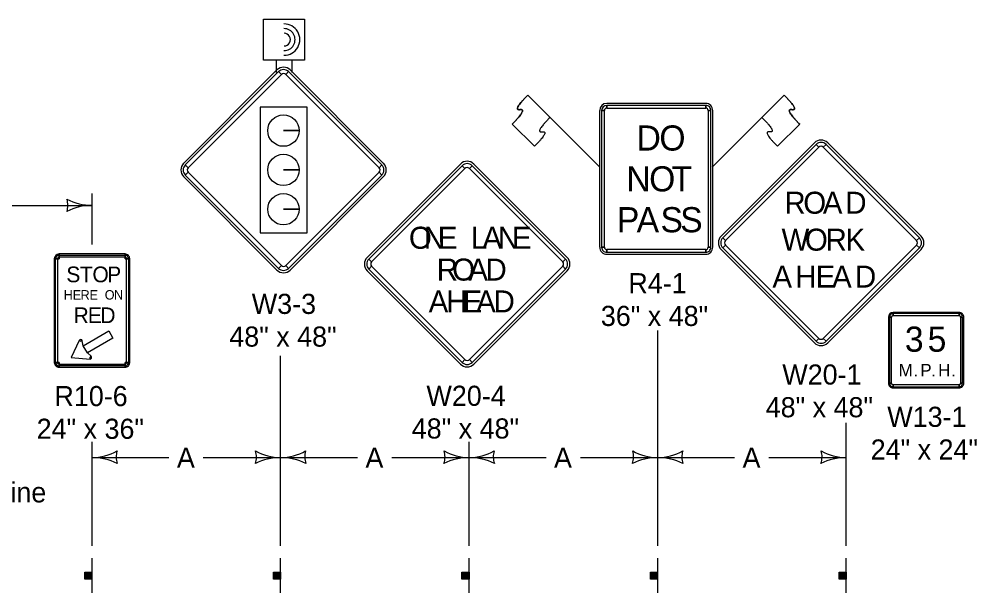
# Model space of a CAD drawing. Extents: x 10124 to 16850, y 7924 to 12166.
# Drawn here: x 16036 to 16798, y 9435 to 9891 of the extents above; entities that cross this region are included whole.
import ezdxf

# ---------------------------------------------------------------- set-up
doc = ezdxf.new("R2010")
doc.units = 0
for name, color, linetype in [('dsnCellElements', 7, 'Continuous'), ('dsnStdLabel', 7, 'Continuous'), ('Level 2', 7, 'Continuous'), ('Level 5', 7, 'Continuous')]:
    doc.layers.add(name, color=color, linetype=linetype)

msp = doc.modelspace()

# ---------------------------------------------------------------- linework, layer by layer
at = {"layer": 'dsnCellElements'}
for centre, radius, start, end in [((16058.64, 9742.96), 16.42, 342.26665, 17.73335), ((16094.27, 9785.46), 42.5, 241.92751, 270), ((16094.27, 9700.46), 42.5, 90, 118.07249)]:
    msp.add_arc(centre, radius, start, end, dxfattribs=at)
at = {"layer": 'dsnStdLabel'}
for p, q in [((16241.35, 9850.62), (16167.1, 9776.37)), ((16242.67, 9849.29), (16244.88, 9847.08)), ((16248.42, 9847.08), (16250.63, 9849.29)), ((16326.2, 9776.37), (16251.95, 9850.62)), ((16498.25, 9773.27), (16440.92, 9830.57)), ((16440.92, 9830.57), (16458.61, 9812.89)), ((16587.55, 9773.27), (16644.87, 9830.58)), ((16644.87, 9830.58), (16627.18, 9812.9)), ((16582.5, 9824.03), (16503.75, 9824.03)), ((16503.75, 9820.28), (16503.75, 9822.46)), ((16582.5, 9822.46), (16582.5, 9820.28)), ((16498.12, 9818.4), (16498.12, 9709.65)), ((16499.68, 9818.4), (16501.87, 9818.4)), ((16584.37, 9818.4), (16586.56, 9818.4)), ((16588.12, 9709.65), (16588.12, 9818.4)), ((16446.23, 9789.9), (16428.55, 9807.57)), ((16639.57, 9789.91), (16657.24, 9807.59)), ((16259.06, 9802.4), (16246.56, 9802.4)), ((16246.56, 9802.4), (16259.06, 9802.4)), ((16668.97, 9792.72), (16594.72, 9718.47)), ((16670.29, 9791.39), (16672.5, 9789.18)), ((16676.04, 9789.18), (16678.25, 9791.39)), ((16753.82, 9718.47), (16679.57, 9792.72)), ((16387.38, 9775.8), (16313.14, 9701.55)), ((16472.24, 9701.55), (16397.99, 9775.8)), ((16170.63, 9772.84), (16168.42, 9775.05)), ((16168.42, 9767.09), (16170.63, 9769.3)), ((16259.06, 9771.15), (16246.56, 9771.15)), ((16246.56, 9771.15), (16259.06, 9771.15)), ((16324.87, 9775.05), (16322.66, 9772.84)), ((16322.66, 9769.3), (16324.87, 9767.09)), ((16388.71, 9774.48), (16390.92, 9772.27)), ((16394.45, 9772.27), (16396.66, 9774.48)), ((16167.1, 9765.77), (16241.35, 9691.52)), ((16251.95, 9691.52), (16326.2, 9765.77)), ((16259.06, 9739.9), (16246.56, 9739.9)), ((16246.56, 9739.9), (16259.06, 9739.9)), ((16598.26, 9714.94), (16596.05, 9717.15)), ((16752.49, 9717.15), (16750.29, 9714.94)), ((16501.87, 9709.65), (16499.68, 9709.65)), ((16503.75, 9705.59), (16503.75, 9707.78)), ((16582.5, 9707.78), (16582.5, 9705.59)), ((16586.56, 9709.65), (16584.37, 9709.65)), ((16594.72, 9707.86), (16668.97, 9633.62)), ((16596.05, 9709.19), (16598.26, 9711.4)), ((16679.57, 9633.62), (16753.82, 9707.86)), ((16750.29, 9711.4), (16752.49, 9709.19)), ((16064.27, 9700.53), (16068.02, 9700.53)), ((16065.21, 9700.53), (16066.77, 9700.53)), ((16068.02, 9700.53), (16068.02, 9704.28)), ((16068.02, 9701.78), (16068.02, 9703.34)), ((16120.52, 9704.28), (16120.52, 9700.53)), ((16120.52, 9703.34), (16120.52, 9701.78)), ((16120.52, 9700.53), (16124.27, 9700.53)), ((16121.77, 9700.53), (16123.34, 9700.53)), ((16316.67, 9698.02), (16314.46, 9700.23)), ((16470.91, 9700.23), (16468.7, 9698.02)), ((16503.75, 9704.03), (16582.5, 9704.03)), ((16244.88, 9695.05), (16242.67, 9692.85)), ((16250.63, 9692.85), (16248.42, 9695.05)), ((16314.46, 9692.27), (16316.67, 9694.48)), ((16468.7, 9694.48), (16470.91, 9692.27)), ((16313.14, 9690.95), (16387.38, 9616.7)), ((16397.99, 9616.7), (16472.24, 9690.95)), ((16727.79, 9654.03), (16727.79, 9601.53)), ((16728.73, 9654.03), (16730.29, 9654.03)), ((16784.04, 9657.78), (16731.54, 9657.78)), ((16731.54, 9655.28), (16731.54, 9656.84)), ((16784.04, 9656.84), (16784.04, 9655.28)), ((16785.29, 9654.03), (16786.85, 9654.03)), ((16787.79, 9601.53), (16787.79, 9654.03)), ((16084.13, 9635.55), (16085.24, 9634.97)), ((16085.24, 9634.97), (16086.46, 9635.24)), ((16672.5, 9637.15), (16670.29, 9634.94)), ((16678.25, 9634.94), (16676.04, 9637.15)), ((16093.58, 9622.9), (16092.74, 9621.98)), ((16068.02, 9618.03), (16064.27, 9618.03)), ((16066.77, 9618.03), (16065.21, 9618.03)), ((16068.02, 9614.28), (16068.02, 9618.03)), ((16068.02, 9615.22), (16068.02, 9616.78)), ((16092.74, 9621.98), (16092.69, 9620.73)), ((16124.27, 9618.03), (16120.52, 9618.03)), ((16120.52, 9618.03), (16120.52, 9614.28)), ((16120.52, 9616.78), (16120.52, 9615.22)), ((16123.34, 9618.03), (16121.77, 9618.03)), ((16390.92, 9620.24), (16388.71, 9618.03)), ((16396.66, 9618.03), (16394.45, 9620.24)), ((16730.29, 9601.53), (16728.73, 9601.53)), ((16731.54, 9598.72), (16731.54, 9600.28)), ((16784.04, 9600.28), (16784.04, 9598.72)), ((16786.85, 9601.53), (16785.29, 9601.53)), ((16731.54, 9597.78), (16784.04, 9597.78))]:
    msp.add_line(p, q, dxfattribs=at)
for points in [[(16242.67, 9849.29), (16168.42, 9775.05), (16170.63, 9772.84), (16244.88, 9847.08), (16242.67, 9849.29)], [(16324.87, 9775.05), (16250.63, 9849.29), (16248.42, 9847.08), (16322.66, 9772.84), (16324.87, 9775.05)], [(16265.38, 9821.01), (16227.92, 9821.01), (16227.92, 9721.12), (16265.38, 9721.12), (16265.38, 9821.01)], [(16582.5, 9822.46), (16503.75, 9822.46), (16503.75, 9820.28), (16582.5, 9820.28), (16582.5, 9822.46)], [(16499.68, 9818.4), (16499.68, 9709.65), (16501.87, 9709.65), (16501.87, 9818.4), (16499.68, 9818.4)], [(16586.56, 9709.65), (16586.56, 9818.4), (16584.37, 9818.4), (16584.37, 9709.65), (16586.56, 9709.65)], [(16670.29, 9791.39), (16596.05, 9717.15), (16598.26, 9714.94), (16672.5, 9789.18), (16670.29, 9791.39)], [(16752.49, 9717.15), (16678.25, 9791.39), (16676.04, 9789.18), (16750.29, 9714.94), (16752.49, 9717.15)], [(16168.42, 9767.09), (16242.67, 9692.85), (16244.88, 9695.05), (16170.63, 9769.3), (16168.42, 9767.09)], [(16250.63, 9692.85), (16324.87, 9767.09), (16322.66, 9769.3), (16248.42, 9695.05), (16250.63, 9692.85)], [(16388.71, 9774.48), (16314.46, 9700.23), (16316.67, 9698.02), (16390.92, 9772.27), (16388.71, 9774.48)], [(16470.91, 9700.23), (16396.66, 9774.48), (16394.45, 9772.27), (16468.7, 9698.02), (16470.91, 9700.23)], [(16503.75, 9705.59), (16582.5, 9705.59), (16582.5, 9707.78), (16503.75, 9707.78), (16503.75, 9705.59)], [(16596.05, 9709.19), (16670.29, 9634.94), (16672.5, 9637.15), (16598.26, 9711.4), (16596.05, 9709.19)], [(16678.25, 9634.94), (16752.49, 9709.19), (16750.29, 9711.4), (16676.04, 9637.15), (16678.25, 9634.94)], [(16068.02, 9614.28), (16120.52, 9614.28), (16120.52, 9618.03), (16124.27, 9618.03), (16124.27, 9700.53), (16120.52, 9700.53), (16120.52, 9704.28), (16068.02, 9704.28), (16068.02, 9700.53), (16064.27, 9700.53), (16064.27, 9618.03), (16068.02, 9618.03), (16068.02, 9614.28)], [(16066.77, 9700.53), (16066.77, 9618.03), (16065.21, 9618.03), (16065.21, 9700.53), (16066.77, 9700.53)], [(16120.52, 9701.78), (16068.02, 9701.78), (16068.02, 9703.34), (16120.52, 9703.34), (16120.52, 9701.78)], [(16121.77, 9618.03), (16121.77, 9700.53), (16123.34, 9700.53), (16123.34, 9618.03), (16121.77, 9618.03)], [(16314.46, 9692.27), (16388.71, 9618.03), (16390.92, 9620.24), (16316.67, 9694.48), (16314.46, 9692.27)], [(16396.66, 9618.03), (16470.91, 9692.27), (16468.7, 9694.48), (16394.45, 9620.24), (16396.66, 9618.03)], [(16728.73, 9654.03), (16728.73, 9601.53), (16730.29, 9601.53), (16730.29, 9654.03), (16728.73, 9654.03)], [(16784.04, 9656.84), (16731.54, 9656.84), (16731.54, 9655.28), (16784.04, 9655.28), (16784.04, 9656.84)], [(16786.85, 9601.53), (16786.85, 9654.03), (16785.29, 9654.03), (16785.29, 9601.53), (16786.85, 9601.53)], [(16107.64, 9643.03), (16110.93, 9637.35), (16090.62, 9625.63), (16087.34, 9631.31), (16107.64, 9643.03)], [(16077.62, 9621.91), (16092.69, 9620.73), (16092.74, 9621.98), (16093.58, 9622.9), (16090.62, 9625.63), (16087.34, 9631.31), (16086.46, 9635.24), (16085.24, 9634.97), (16084.13, 9635.55), (16077.62, 9621.91)], [(16068.02, 9616.78), (16120.52, 9616.78), (16120.52, 9615.22), (16068.02, 9615.22), (16068.02, 9616.78)], [(16731.54, 9598.72), (16784.04, 9598.72), (16784.04, 9600.28), (16731.54, 9600.28), (16731.54, 9598.72)]]:
    msp.add_lwpolyline(points, close=True, dxfattribs=at)
for centre in [(16246.56, 9802.4), (16246.56, 9771.15), (16246.56, 9739.9)]:
    msp.add_circle(centre, 12.5, dxfattribs=at)
for centre, radius, start, end in [((16246.65, 9845.31), 7.5, 44.99999, 134.99974), ((16246.65, 9845.31), 5.62, 44.99999, 134.99974), ((16246.65, 9845.31), 2.5, 44.99999, 134.99974), ((16503.75, 9818.4), 5.62, 90.00021, 179.99985), ((16503.75, 9818.4), 4.06, 90.00021, 179.99985), ((16582.5, 9818.4), 5.62, 0, 90.00021), ((16582.5, 9818.4), 4.06, 0, 90.00021), ((16503.75, 9818.4), 1.87, 90.00021, 179.99985), ((16582.5, 9818.4), 1.87, 0, 90.00021), ((16674.27, 9787.41), 7.5, 44.99999, 134.99974), ((16674.27, 9787.41), 5.62, 44.99999, 134.99974), ((16674.27, 9787.41), 2.5, 44.99999, 134.99974), ((16172.4, 9771.07), 7.5, 134.99974, 224.99995), ((16320.89, 9771.07), 7.5, 315.00016, 44.9998), ((16392.69, 9770.5), 7.5, 44.99999, 134.99974), ((16392.69, 9770.5), 5.62, 44.99999, 134.99974), ((16172.4, 9771.07), 5.62, 134.99974, 224.99995), ((16172.4, 9771.07), 2.5, 134.99974, 224.99995), ((16320.89, 9771.07), 2.5, 315.00016, 44.9998), ((16320.89, 9771.07), 5.62, 315.00016, 44.9998), ((16392.69, 9770.5), 2.5, 44.99999, 134.99974), ((16600.03, 9713.17), 7.5, 134.99974, 224.99995), ((16600.03, 9713.17), 5.62, 134.99974, 224.99995), ((16600.03, 9713.17), 2.5, 134.99974, 224.99995), ((16748.52, 9713.17), 2.5, 315.00016, 44.9998), ((16748.52, 9713.17), 5.62, 315.00016, 44.9998), ((16748.52, 9713.17), 7.5, 315.00016, 44.9998), ((16503.75, 9709.65), 5.62, 179.99985, 270.00006), ((16503.75, 9709.65), 4.06, 179.99985, 270.00006), ((16503.75, 9709.65), 1.87, 179.99985, 270.00006), ((16582.5, 9709.65), 5.62, 270.00006, 0.00027), ((16582.5, 9709.65), 4.06, 270.00006, 0.00027), ((16582.5, 9709.65), 1.87, 270.00006, 0.00027), ((16068.02, 9700.53), 3.75, 90.00021, 179.99985), ((16068.02, 9700.53), 2.81, 90.00021, 179.99985), ((16068.02, 9700.53), 1.25, 90.00021, 179.99985), ((16120.52, 9700.53), 3.75, 0, 90.00021), ((16120.52, 9700.53), 2.81, 0, 90.00021), ((16120.52, 9700.53), 1.25, 0, 90.00021), ((16318.44, 9696.25), 7.5, 134.99974, 224.99995), ((16318.44, 9696.25), 5.62, 134.99974, 224.99995), ((16466.93, 9696.25), 5.62, 315.00016, 44.9998), ((16466.93, 9696.25), 7.5, 315.00016, 44.9998), ((16246.65, 9696.82), 7.5, 224.99995, 315.00016), ((16246.65, 9696.82), 5.62, 224.99995, 315.00016), ((16246.65, 9696.82), 2.5, 224.99995, 315.00016), ((16318.44, 9696.25), 2.5, 134.99974, 224.99995), ((16466.93, 9696.25), 2.5, 315.00016, 44.9998), ((16731.54, 9654.03), 3.75, 90.00021, 179.99985), ((16731.54, 9654.03), 2.81, 90.00021, 179.99985), ((16731.54, 9654.03), 1.25, 90.00021, 179.99985), ((16784.04, 9654.03), 3.75, 0, 90.00021), ((16784.04, 9654.03), 2.81, 0, 90.00021), ((16784.04, 9654.03), 1.25, 0, 90.00021), ((16085.24, 9634.97), 1.25, 12.62232, 152.27557), ((16674.27, 9638.92), 7.5, 224.99995, 315.00016), ((16674.27, 9638.92), 5.62, 224.99995, 315.00016), ((16674.27, 9638.92), 2.5, 224.99995, 315.00016), ((16092.74, 9621.98), 1.25, 267.72427, 47.37758), ((16068.02, 9618.03), 3.75, 179.99985, 270.00006), ((16068.02, 9618.03), 2.81, 179.99985, 270.00006), ((16068.02, 9618.03), 1.25, 179.99985, 270.00006), ((16120.52, 9618.03), 3.75, 270.00006, 0.00027), ((16120.52, 9618.03), 2.81, 270.00006, 0.00027), ((16120.52, 9618.03), 1.25, 270.00006, 0.00027), ((16392.69, 9622.01), 7.5, 224.99995, 315.00016), ((16392.69, 9622.01), 5.62, 224.99995, 315.00016), ((16392.69, 9622.01), 2.5, 224.99995, 315.00016), ((16731.54, 9601.53), 3.75, 179.99985, 270.00006), ((16731.54, 9601.53), 2.81, 179.99985, 270.00006), ((16731.54, 9601.53), 1.25, 179.99985, 270.00006), ((16784.04, 9601.53), 3.75, 270.00006, 0.00027), ((16784.04, 9601.53), 2.81, 270.00006, 0.00027), ((16784.04, 9601.53), 1.25, 270.00006, 0.00027)]:
    msp.add_arc(centre, radius, start, end, dxfattribs=at)
for points in [[(16428.55, 9807.57), (16440.92, 9819.95), (16428.55, 9818.18), (16440.92, 9830.57)], [(16657.24, 9807.59), (16644.87, 9819.97), (16657.24, 9818.2), (16644.87, 9830.58)], [(16458.61, 9812.89), (16446.23, 9800.5), (16458.6, 9802.28), (16446.23, 9789.9)], [(16627.18, 9812.9), (16639.56, 9800.52), (16627.19, 9802.29), (16639.57, 9789.91)]]:
    msp.add_open_spline(points, degree=2, dxfattribs=at)
at = {"layer": 'Level 2'}
for p, q in [((16240.8, 9858.53), (16240.8, 9848.53)), ((16253.3, 9858.53), (16253.3, 9848.53)), ((16094.27, 9711.85), (16094.27, 9752.26)), ((15430.7, 9742.96), (16094.27, 9742.96)), ((16544.27, 9472.29), (16544.27, 9643.52)), ((16244.27, 9472.29), (16244.27, 9623.19)), ((16694.27, 9472.29), (16694.27, 9569.97)), ((16094.27, 9472.29), (16094.27, 9554.79)), ((16394.27, 9472.29), (16394.27, 9554.79)), ((16094.27, 9542.29), (16155.44, 9542.29)), ((16182.78, 9542.29), (16244.27, 9542.29)), ((16244.27, 9542.29), (16305.44, 9542.29)), ((16332.78, 9542.29), (16394.27, 9542.29)), ((16394.27, 9542.29), (16455.44, 9542.29)), ((16482.78, 9542.29), (16544.27, 9542.29)), ((16544.27, 9542.29), (16605.44, 9542.29)), ((16632.78, 9542.29), (16694.27, 9542.29)), ((16094.27, 9434.79), (16094.27, 9462.29)), ((16244.27, 9434.79), (16244.27, 9462.29)), ((16394.27, 9434.79), (16394.27, 9462.29)), ((16544.27, 9434.79), (16544.27, 9462.29)), ((16694.27, 9434.79), (16694.27, 9462.29)), ((16088.95, 9445.65), (16088.95, 9451.23)), ((16089.27, 9451.23), (16089.27, 9445.65)), ((16089.49, 9445.65), (16089.49, 9451.23)), ((16089.81, 9451.23), (16089.81, 9445.65)), ((16090.03, 9445.65), (16090.02, 9451.23)), ((16090.45, 9451.23), (16090.47, 9445.65)), ((16090.67, 9445.65), (16090.67, 9451.23)), ((16091.1, 9451.23), (16091.1, 9445.65)), ((16091.48, 9445.65), (16091.48, 9451.23)), ((16091.8, 9451.23), (16091.82, 9445.65)), ((16092.02, 9445.65), (16092.02, 9451.23)), ((16092.29, 9451.23), (16092.29, 9445.65)), ((16092.62, 9445.65), (16092.62, 9451.23)), ((16092.83, 9451.23), (16092.83, 9445.65)), ((16093.05, 9445.65), (16093.05, 9451.23)), ((16093.32, 9451.23), (16093.32, 9445.65)), ((16093.58, 9445.65), (16093.58, 9451.23)), ((16093.86, 9451.23), (16093.86, 9445.65)), ((16238.95, 9445.65), (16238.95, 9451.23)), ((16239.27, 9451.23), (16239.27, 9445.65)), ((16239.49, 9445.65), (16239.49, 9451.23)), ((16239.81, 9451.23), (16239.81, 9445.65)), ((16240.03, 9445.65), (16240.02, 9451.23)), ((16240.45, 9451.23), (16240.47, 9445.65)), ((16240.67, 9445.65), (16240.67, 9451.23)), ((16241.1, 9451.23), (16241.1, 9445.65)), ((16241.48, 9445.65), (16241.48, 9451.23)), ((16241.8, 9451.23), (16241.82, 9445.65)), ((16242.02, 9445.65), (16242.02, 9451.23)), ((16242.28, 9451.23), (16242.28, 9445.65)), ((16242.62, 9445.65), (16242.62, 9451.23)), ((16242.83, 9451.23), (16242.83, 9445.65)), ((16243.05, 9445.65), (16243.05, 9451.23)), ((16243.32, 9451.23), (16243.32, 9445.65)), ((16243.58, 9445.65), (16243.58, 9451.23)), ((16243.86, 9451.23), (16243.86, 9445.65)), ((16388.95, 9445.65), (16388.95, 9451.23)), ((16389.27, 9451.23), (16389.27, 9445.65)), ((16389.49, 9445.65), (16389.49, 9451.23)), ((16389.81, 9451.23), (16389.81, 9445.65)), ((16390.03, 9445.65), (16390.02, 9451.23)), ((16390.45, 9451.23), (16390.47, 9445.65)), ((16390.67, 9445.65), (16390.67, 9451.23)), ((16391.1, 9451.23), (16391.1, 9445.65)), ((16391.48, 9445.65), (16391.48, 9451.23)), ((16391.8, 9451.23), (16391.82, 9445.65)), ((16392.02, 9445.65), (16392.02, 9451.23)), ((16392.28, 9451.23), (16392.28, 9445.65)), ((16392.62, 9445.65), (16392.62, 9451.23)), ((16392.83, 9451.23), (16392.83, 9445.65)), ((16393.05, 9445.65), (16393.05, 9451.23)), ((16393.32, 9451.23), (16393.32, 9445.65)), ((16393.58, 9445.65), (16393.58, 9451.23)), ((16393.86, 9451.23), (16393.86, 9445.65)), ((16538.95, 9445.65), (16538.95, 9451.23)), ((16539.27, 9451.23), (16539.27, 9445.65)), ((16539.49, 9445.65), (16539.49, 9451.23)), ((16539.81, 9451.23), (16539.81, 9445.65)), ((16540.03, 9445.65), (16540.02, 9451.23)), ((16540.45, 9451.23), (16540.47, 9445.65)), ((16540.67, 9445.65), (16540.67, 9451.23)), ((16541.1, 9451.23), (16541.1, 9445.65)), ((16541.48, 9445.65), (16541.48, 9451.23)), ((16541.8, 9451.23), (16541.82, 9445.65)), ((16542.02, 9445.65), (16542.02, 9451.23)), ((16542.28, 9451.23), (16542.28, 9445.65)), ((16542.62, 9445.65), (16542.62, 9451.23)), ((16542.83, 9451.23), (16542.83, 9445.65)), ((16543.05, 9445.65), (16543.05, 9451.23)), ((16543.32, 9451.23), (16543.32, 9445.65)), ((16543.58, 9445.65), (16543.58, 9451.23)), ((16543.86, 9451.23), (16543.86, 9445.65)), ((16688.95, 9445.65), (16688.95, 9451.23)), ((16689.26, 9451.23), (16689.26, 9445.65)), ((16689.49, 9445.65), (16689.49, 9451.23)), ((16689.81, 9451.23), (16689.81, 9445.65)), ((16690.03, 9445.65), (16690.01, 9451.23)), ((16690.45, 9451.23), (16690.46, 9445.65)), ((16690.67, 9445.65), (16690.67, 9451.23)), ((16691.1, 9451.23), (16691.1, 9445.65)), ((16691.48, 9445.65), (16691.48, 9451.23)), ((16691.8, 9451.23), (16691.81, 9445.65)), ((16692.02, 9445.65), (16692.02, 9451.23)), ((16692.28, 9451.23), (16692.28, 9445.65)), ((16692.62, 9445.65), (16692.62, 9451.23)), ((16692.83, 9451.23), (16692.83, 9445.65)), ((16693.05, 9445.65), (16693.05, 9451.23)), ((16693.31, 9451.23), (16693.31, 9445.65)), ((16693.58, 9445.65), (16693.58, 9451.23)), ((16693.86, 9451.23), (16693.86, 9445.65))]:
    msp.add_line(p, q, dxfattribs=at)
for points in [[(16230.8, 9858.53), (16230.8, 9891.03), (16263.3, 9891.03), (16263.3, 9858.53)], [(16094.18, 9451.23), (16094.18, 9445.61), (16088.55, 9445.61), (16088.55, 9451.23)], [(16244.18, 9451.23), (16244.18, 9445.61), (16238.55, 9445.61), (16238.55, 9451.23)], [(16394.18, 9451.23), (16394.18, 9445.61), (16388.55, 9445.61), (16388.55, 9451.23)], [(16544.18, 9451.23), (16544.18, 9445.61), (16538.55, 9445.61), (16538.55, 9451.23)], [(16694.18, 9451.23), (16694.18, 9445.61), (16688.55, 9445.61), (16688.55, 9451.23)]]:
    msp.add_lwpolyline(points, close=True, dxfattribs=at)
for centre, radius, start, end in [((16247.06, 9874.77), 12.5, 269.40414, 90.54446), ((16247.06, 9874.77), 12.5, 269.40414, 90.54446), ((16247.06, 9874.77), 8.75, 269.40414, 90.54446), ((16247.06, 9874.77), 5, 269.40414, 90.54446), ((16093.52, 9584.78), 42.5, 271.0176, 299.07249), ((16129.89, 9542.91), 16.42, 163.26665, 198.73335), ((16208.66, 9542.91), 16.42, 341.26665, 16.73335), ((16245.03, 9584.78), 42.5, 240.92751, 268.9824), ((16243.52, 9584.78), 42.5, 271.0176, 299.07249), ((16279.89, 9542.91), 16.42, 163.26665, 198.73335), ((16358.66, 9542.91), 16.42, 341.26665, 16.73335), ((16395.03, 9584.78), 42.5, 240.92751, 268.9824), ((16393.52, 9584.78), 42.5, 271.0176, 299.07249), ((16429.89, 9542.91), 16.42, 163.26665, 198.73335), ((16508.66, 9542.91), 16.42, 341.26665, 16.73335), ((16545.03, 9584.78), 42.5, 240.92751, 268.9824), ((16543.52, 9584.78), 42.5, 271.0176, 299.07249), ((16579.89, 9542.91), 16.42, 163.26665, 198.73335), ((16658.65, 9542.91), 16.42, 341.26665, 16.73335), ((16695.03, 9584.78), 42.5, 240.92751, 268.9824), ((16095, 9499.79), 42.5, 62.92751, 90.9824), ((16243.54, 9499.79), 42.5, 89.0176, 117.07249), ((16245, 9499.79), 42.5, 62.92751, 90.9824), ((16393.54, 9499.79), 42.5, 89.0176, 117.07249), ((16395, 9499.79), 42.5, 62.92751, 90.9824), ((16543.54, 9499.79), 42.5, 89.0176, 117.07249), ((16545, 9499.79), 42.5, 62.92751, 90.9824), ((16693.54, 9499.79), 42.5, 89.0176, 117.07249)]:
    msp.add_arc(centre, radius, start, end, dxfattribs=at)
at = {"layer": 'Level 5'}
for p, q in [((16428.55, 9807.57), (16446.23, 9789.9)), ((16657.24, 9807.59), (16639.57, 9789.91))]:
    msp.add_line(p, q, dxfattribs=at)
for points in [[(16440.92, 9830.57), (16428.55, 9818.18), (16440.92, 9819.95), (16428.55, 9807.57)], [(16644.87, 9830.58), (16657.24, 9818.2), (16644.87, 9819.97), (16657.24, 9807.59)], [(16458.61, 9812.89), (16446.23, 9800.5), (16458.6, 9802.28), (16446.23, 9789.9)], [(16627.18, 9812.9), (16639.56, 9800.52), (16627.19, 9802.29), (16639.57, 9789.91)]]:
    msp.add_open_spline(points, degree=2, dxfattribs=at)

# ---------------------------------------------------------------- texts
at = {"layer": 'dsnStdLabel'}
for s, height, p in [('D', 20, (16527.5, 9786.53)), ('O', 20, (16545.62, 9786.53)), ('N', 20, (16519.37, 9754.03)), ('O', 20, (16537.5, 9754.03)), ('T', 20, (16555.31, 9754.03)), ('R', 17.5, (16645.11, 9736.29)), ('O', 17.5, (16660.12, 9736.29)), ('A', 17.5, (16675.67, 9736.29)), ('D', 17.5, (16693.55, 9736.29)), ('P', 20, (16511.85, 9721.53)), ('A', 20, (16527.54, 9721.53)), ('S', 20, (16546.51, 9721.53)), ('S', 20, (16562.2, 9721.53)), ('O', 17.5, (16346.4, 9708.44)), ('N', 17.5, (16358.18, 9708.44)), ('E', 17.5, (16369.4, 9708.44)), ('L', 17.5, (16395.65, 9708.44)), ('A', 17.5, (16404.85, 9708.44)), ('N', 17.5, (16417.12, 9708.44)), ('E', 17.5, (16428.35, 9708.44)), ('W', 17.5, (16642.82, 9706.92)), ('O', 17.5, (16661.42, 9706.92)), ('R', 17.5, (16677.83, 9706.92)), ('K', 17.5, (16693.69, 9706.92)), ('R', 17.5, (16368.51, 9683.13)), ('O', 17.5, (16380.8, 9683.13)), ('A', 17.5, (16393.64, 9683.13)), ('D', 17.5, (16407.29, 9683.13)), ('S', 12.5, (16073.82, 9681.78)), ('T', 12.5, (16084.59, 9681.78)), ('O', 12.5, (16094.57, 9681.78)), ('P', 12.5, (16106.32, 9681.78)), ('A', 17.5, (16635.55, 9677.54)), ('H', 17.5, (16653.75, 9677.54)), ('E', 17.5, (16669.98, 9677.54)), ('A', 17.5, (16683.03, 9677.54)), ('D', 17.5, (16701.24, 9677.54)), ('H', 7.5, (16071.75, 9668.03)), ('E', 7.5, (16078.9, 9668.03)), ('R', 7.5, (16085.16, 9668.03)), ('E', 7.5, (16092.3, 9668.03)), ('O', 7.5, (16104.37, 9668.03)), ('N', 7.5, (16111.76, 9668.03)), ('A', 17.5, (16362.07, 9657.81)), ('H', 17.5, (16375.94, 9657.81)), ('E', 17.5, (16389.15, 9657.81)), ('A', 17.5, (16399.87, 9657.81)), ('D', 17.5, (16413.73, 9657.81)), ('R', 12.5, (16079.59, 9649.28)), ('E', 12.5, (16090.91, 9649.28)), ('D', 12.5, (16100.88, 9649.28)), ('3', 20, (16740.94, 9626.54)), ('5', 20, (16759.06, 9626.54)), ('M', 10, (16736.02, 9606.84)), ('P', 10, (16753.27, 9606.84)), ('H', 10, (16767.39, 9606.84)), ('.', 10, (16747.81, 9606.84)), ('.', 10, (16761.93, 9606.84)), ('.', 10, (16777.86, 9606.84))]:
    msp.add_text(s, height=height, dxfattribs=at).set_placement(p)
at = {"layer": 'Level 2'}
for s, p in [('R4-1', (16520.96, 9673.03)), ('W3-3', (16221.36, 9656.6)), ('36" x 48"', (16499.05, 9647.03)), ('48" x 48"', (16203.48, 9630.6)), ('W20-1', (16643.42, 9600.42)), ('R10-6', (16064.35, 9583.28)), ('W20-4', (16360.32, 9583.51)), ('48" x 48"', (16630.21, 9574.42)), ('W13-1', (16726.94, 9566.78)), ('24" x 36"', (16050.21, 9557.28)), ('48" x 48"', (16348.62, 9557.51)), ('24" x 24"', (16713.73, 9540.78)), ('A', (16161.8, 9534.29)), ('A', (16311.8, 9534.29)), ('A', (16461.8, 9534.29)), ('A', (16611.8, 9534.29)), ('Edge Line', (15961.51, 9506.72))]:
    msp.add_text(s, height=16, dxfattribs=at).set_placement(p)

doc.saveas('drawing.dxf')
